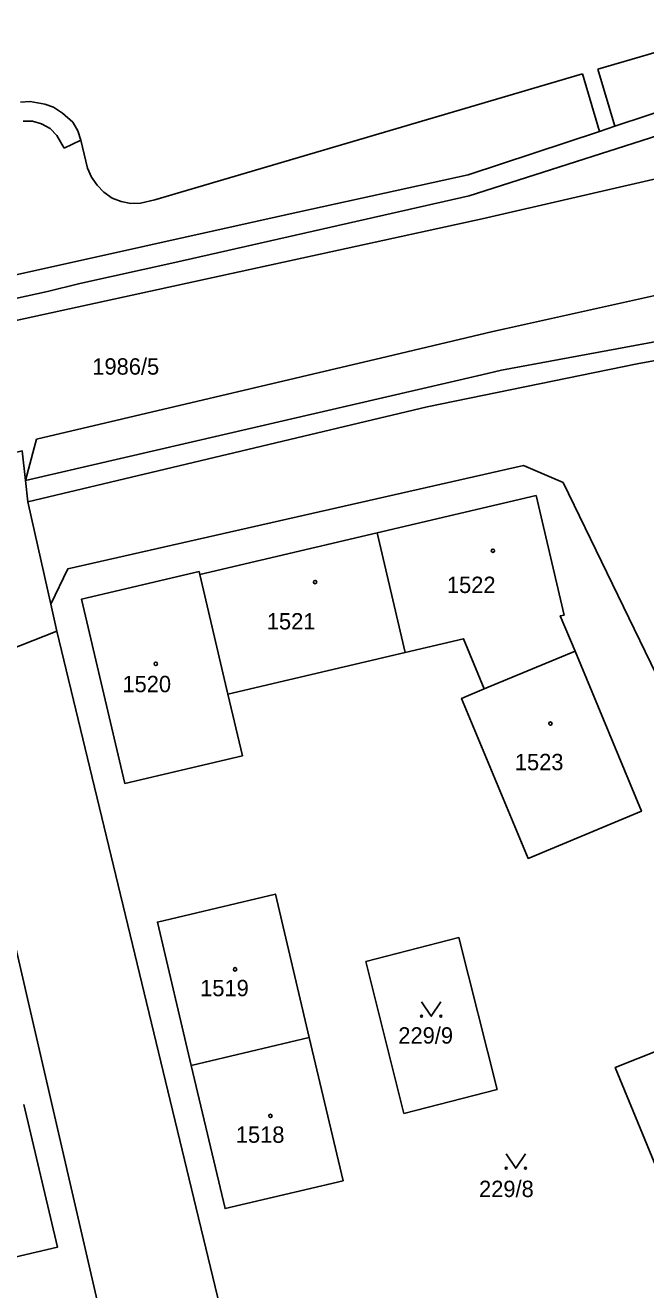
# Model space of a CAD drawing. Extents: x -679220 to -673243, y -1075091 to -1066557.
# Drawn here: x -676014.5 to -675950, y -1071652.9 to -1071521.5 of the extents above; entities that cross this region are included whole.
import ezdxf

# ---------------------------------------------------------------- set-up
doc = ezdxf.new("R2010")
doc.units = 0
for name, color, linetype in [('Hranice parcel', 7, 'Continuous'), ('Parcelní čísla', 7, 'Continuous'), ('Vnitřní kresba', 7, 'Continuous'), ('Značky budov', 7, 'Continuous'), ('Značky kultur', 7, 'Continuous')]:
    doc.layers.add(name, color=color, linetype=linetype)

msp = doc.modelspace()

# ---------------------------------------------------------------- linework, layer by layer
at = {"layer": 'Hranice parcel'}
for p, q in [((-676011.87, -1071581.65), (-676014.26, -1071571.02)), ((-675977.93, -1071574.24), (-675996.38, -1071578.57)), ((-675975.02, -1071586.67), (-675977.93, -1071574.24)), ((-675993.46, -1071591), (-675996.38, -1071578.57)), ((-676011.23, -1071584.45), (-676011.87, -1071581.65)), ((-676021.74, -1071588.6), (-676011.23, -1071584.45)), ((-675993.46, -1071591), (-675975.02, -1071586.67)), ((-675966.8, -1071590.47), (-675957.37, -1071586.56)), ((-675984.99, -1071626.7), (-675997.26, -1071629.6))]:
    msp.add_line(p, q, dxfattribs=at)
for points in [[(-676016.9, -1071547.75), (-675987.28, -1071541.17), (-675968.47, -1071537.02), (-675954.84, -1071532.51), (-675953.23, -1071531.98), (-675923, -1071521.98), (-675892.45, -1071512.39), (-675869.31, -1071507.45)], [(-675837.15, -1071533.74), (-675848.11, -1071538.72), (-675877.36, -1071543.69), (-675912.93, -1071549.73), (-675950.9, -1071556.66), (-675972.74, -1071561.14), (-676014.26, -1071571.02)], [(-676014.26, -1071571.02), (-676014.5, -1071568.8), (-676014.83, -1071565.73), (-676024.22, -1071568.12)], [(-676011.87, -1071581.65), (-676010.11, -1071577.99), (-675962.74, -1071567.26), (-675958.61, -1071569.02), (-675920.48, -1071647.57), (-675919.65, -1071652.44), (-675920, -1071652.79)], [(-675957.37, -1071586.56), (-675958.91, -1071582.87), (-675958.51, -1071582.8), (-675961.42, -1071570.37), (-675977.93, -1071574.24)], [(-675996.38, -1071578.57), (-675996.45, -1071578.27), (-676008.68, -1071581.15), (-676004.17, -1071600.29), (-675991.94, -1071597.41), (-675993.46, -1071591)], [(-675976.71, -1071708.75), (-675978.03, -1071709.04), (-675980.22, -1071706.33), (-675979.77, -1071703.5), (-675975.35, -1071696.19), (-675986.93, -1071685.2), (-676011.23, -1071584.45)], [(-675975.02, -1071586.67), (-675968.96, -1071585.25), (-675966.8, -1071590.47)], [(-675966.8, -1071590.47), (-675969.17, -1071591.45), (-675962.26, -1071608.09), (-675950.47, -1071603.19), (-675957.37, -1071586.56)], [(-675984.99, -1071626.7), (-675988.51, -1071611.8), (-676000.78, -1071614.7), (-675997.26, -1071629.6)], [(-676016.65, -1071612.42), (-675999.43, -1071687.09), (-676012.49, -1071700.56), (-675988.26, -1071726.86)], [(-675965.46, -1071632.12), (-675975.16, -1071634.59), (-675979.11, -1071618.82), (-675969.44, -1071616.32), (-675965.46, -1071632.12)], [(-675934.54, -1071641.89), (-675941.42, -1071625.16), (-675953.19, -1071629.84), (-675946.31, -1071646.57), (-675943.67, -1071645.52)], [(-675997.26, -1071629.6), (-675993.75, -1071644.49), (-675981.48, -1071641.59), (-675984.99, -1071626.7)], [(-676026.99, -1071636.54), (-676023.47, -1071651.39), (-676011.16, -1071648.49), (-676014.66, -1071633.66)]]:
    msp.add_lwpolyline(points, dxfattribs=at)
at = {"layer": 'Vnitřní kresba'}
for p, q in [((-675923.04, -1071516.66), (-675954.99, -1071526.05)), ((-675968.39, -1071539.22), (-675922.22, -1071524.46)), ((-675954.99, -1071526.05), (-675953.23, -1071531.98)), ((-675956.61, -1071526.52), (-676001.04, -1071539.62)), ((-675954.84, -1071532.51), (-675956.61, -1071526.52)), ((-676014.02, -1071529.4), (-676015.03, -1071529.46)), ((-676012.5, -1071529.69), (-676014.02, -1071529.4)), ((-676011.57, -1071529.99), (-676012.5, -1071529.69)), ((-676010.64, -1071530.62), (-676011.57, -1071529.99)), ((-676013.77, -1071531.45), (-676014.75, -1071531.45)), ((-676012.82, -1071531.72), (-676013.77, -1071531.45)), ((-676009.56, -1071531.57), (-676010.64, -1071530.62)), ((-676009.04, -1071532.45), (-676009.56, -1071531.57)), ((-675967.04, -1071541.6), (-675920.42, -1071530.83)), ((-676011.93, -1071532.22), (-676012.82, -1071531.72)), ((-676011.24, -1071532.93), (-676011.93, -1071532.22)), ((-676010.48, -1071534.26), (-676011.24, -1071532.93)), ((-676008.75, -1071533.43), (-676009.04, -1071532.45)), ((-676008.75, -1071533.43), (-676010.48, -1071534.26)), ((-676008.04, -1071536.33), (-676008.75, -1071533.43)), ((-676007.65, -1071537.28), (-676008.04, -1071536.33)), ((-676007.06, -1071538.09), (-676007.65, -1071537.28)), ((-676006.35, -1071538.84), (-676007.06, -1071538.09)), ((-676005.5, -1071539.44), (-676006.35, -1071538.84)), ((-676004.55, -1071539.79), (-676005.5, -1071539.44)), ((-675968.39, -1071539.22), (-675998.97, -1071546.15)), ((-676003.55, -1071540), (-676004.55, -1071539.79)), ((-676002.53, -1071539.97), (-676003.55, -1071540)), ((-676001.04, -1071539.62), (-676002.53, -1071539.97)), ((-676016.42, -1071552.38), (-675967.04, -1071541.6)), ((-675911.59, -1071541.24), (-675964.48, -1071553.01)), ((-676008.86, -1071548.33), (-675998.97, -1071546.15)), ((-676012.2, -1071549.14), (-676008.86, -1071548.33)), ((-676016.65, -1071550.13), (-676012.2, -1071549.14)), ((-675965.93, -1071553.33), (-675976.88, -1071555.92)), ((-675964.48, -1071553.01), (-675965.93, -1071553.33)), ((-675965.01, -1071557.35), (-675946.38, -1071553.87)), ((-675976.88, -1071555.92), (-676013.34, -1071564.52)), ((-676014.5, -1071568.8), (-675967.06, -1071557.82)), ((-675967.06, -1071557.82), (-675965.01, -1071557.35)), ((-676013.58, -1071565.41), (-676014.5, -1071568.8)), ((-676013.34, -1071564.52), (-676013.58, -1071565.41))]:
    msp.add_line(p, q, dxfattribs=at)
at = {"layer": 'Značky budov'}
for centre in [(-675965.91, -1071576.1), (-675984.39, -1071579.36), (-676000.96, -1071587.86), (-675959.93, -1071594.07), (-675992.71, -1071619.62), (-675989.04, -1071634.85)]:
    msp.add_circle(centre, 0.175, dxfattribs=at)
at = {"layer": 'Značky kultur'}
for points in [[(-675973.32, -1071623), (-675972.32, -1071624.5), (-675971.32, -1071623)], [(-675964.53, -1071638.79), (-675963.53, -1071640.29), (-675962.53, -1071638.79)]]:
    msp.add_lwpolyline(points, dxfattribs=at)
for centre in [(-675973.32, -1071624.5), (-675971.32, -1071624.5), (-675964.53, -1071640.29), (-675962.53, -1071640.29)]:
    msp.add_circle(centre, 0.1, dxfattribs=at)

# ---------------------------------------------------------------- texts
at = {"layer": 'Parcelní čísla'}
for s, p in [('1986/5', (-676007.55, -1071557.8)), ('1522', (-675970.69, -1071580.5)), ('1521', (-675989.41, -1071584.29)), ('1520', (-676004.42, -1071590.81)), ('1523', (-675963.63, -1071598.92)), ('1519', (-675996.34, -1071622.41)), ('229/9', (-675975.74, -1071627.34)), ('1518', (-675992.63, -1071637.65)), ('229/8', (-675967.35, -1071643.29))]:
    msp.add_text(s, height=1.7, dxfattribs=at).set_placement(p)

doc.saveas('drawing.dxf')
